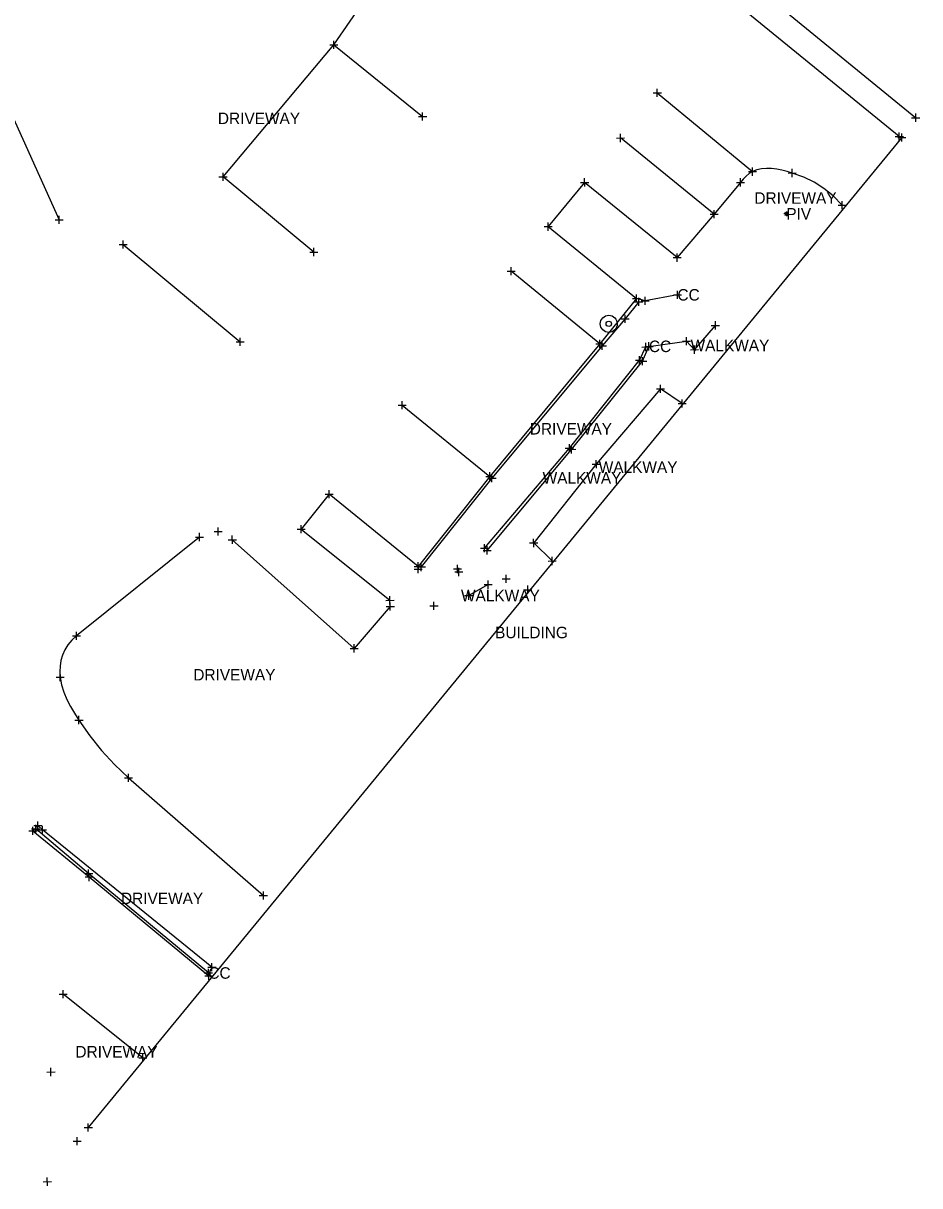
# Model space of a CAD drawing. Extents: x 1729655 to 1739338, y 463812 to 469501.
# Drawn here: x 1736064.5 to 1736204.6, y 466930.5 to 467112.2 of the extents above; entities that cross this region are included whole.
import ezdxf

# ---------------------------------------------------------------- set-up
doc = ezdxf.new("R2010")
doc.units = 0
for name, color, linetype in [('S_Bridge_Column_Round', 7, 'Continuous'), ('S_Bridge_Rail', 7, 'Continuous'), ('S_Buildings_Steps', 7, 'Continuous'), ('S_Ground_SpotElevation', 7, 'Continuous'), ('S_Property_Garden', 7, 'Continuous'), ('S_Roadway_Drive_Gravel', 7, 'Continuous'), ('S_Roadway_Drive_Paved', 7, 'Continuous'), ('S_Roadway_Edge_TW', 7, 'Continuous'), ('S_Roadway_Painted_Lines', 7, 'Continuous'), ('S_Roadway_Sidewalks', 7, 'Continuous'), ('S_Terrain_High_Points', 7, 'Continuous'), ('S_Trees_Bush_Line', 7, 'Continuous')]:
    doc.layers.add(name, color=color, linetype=linetype)

msp = doc.modelspace()

# ---------------------------------------------------------------- linework, layer by layer
at = {"layer": 'S_Bridge_Column_Round'}
for p, q in [((1736112.39, 467108.81), (1736113.66, 467108.81)), ((1736112.39, 467108.81), (1736113.66, 467108.81)), ((1736113.03, 467108.18), (1736113.03, 467109.45)), ((1736113.03, 467108.18), (1736113.03, 467109.45)), ((1736113.03, 467108.81), (1736113.03, 467108.81)), ((1736113.03, 467108.81), (1736113.03, 467108.81)), ((1736162.91, 467101.32), (1736164.19, 467101.32)), ((1736163.55, 467100.69), (1736163.55, 467101.96)), ((1736163.55, 467101.32), (1736163.55, 467101.32)), ((1736126.89, 467096.99), (1736126.89, 467098.26)), ((1736203.92, 467096.8), (1736203.92, 467098.08)), ((1736126.25, 467097.62), (1736127.53, 467097.62)), ((1736126.89, 467097.62), (1736126.89, 467097.62)), ((1736203.28, 467097.44), (1736204.55, 467097.44)), ((1736203.92, 467097.44), (1736203.92, 467097.44)), ((1736157.15, 467094.27), (1736158.42, 467094.28)), ((1736157.79, 467093.64), (1736157.79, 467094.91)), ((1736157.79, 467094.28), (1736157.79, 467094.28)), ((1736200.72, 467094.49), (1736202, 467094.5)), ((1736201.13, 467094.34), (1736202.4, 467094.34)), ((1736201.36, 467093.86), (1736201.36, 467095.13)), ((1736201.36, 467094.5), (1736201.36, 467094.5)), ((1736201.77, 467093.7), (1736201.76, 467094.98)), ((1736201.76, 467094.34), (1736201.76, 467094.34)), ((1736095.7, 467087.56), (1736095.7, 467088.83)), ((1736095.7, 467087.56), (1736095.7, 467088.83)), ((1736177.78, 467089.02), (1736179.05, 467089.02)), ((1736177.78, 467089.02), (1736179.05, 467089.02)), ((1736178.42, 467088.38), (1736178.42, 467089.65)), ((1736178.42, 467088.38), (1736178.42, 467089.65)), ((1736178.42, 467089.02), (1736178.42, 467089.02)), ((1736178.42, 467089.02), (1736178.42, 467089.02)), ((1736184, 467088.8), (1736185.27, 467088.81)), ((1736184.64, 467088.17), (1736184.63, 467089.44)), ((1736184.63, 467088.8), (1736184.63, 467088.8)), ((1736095.06, 467088.2), (1736096.34, 467088.2)), ((1736095.06, 467088.2), (1736096.34, 467088.2)), ((1736095.7, 467088.2), (1736095.7, 467088.2)), ((1736095.7, 467088.2), (1736095.7, 467088.2)), ((1736151.57, 467087.33), (1736152.84, 467087.33)), ((1736152.21, 467086.7), (1736152.2, 467087.97)), ((1736152.2, 467087.33), (1736152.2, 467087.33)), ((1736175.9, 467087.33), (1736177.17, 467087.33)), ((1736176.53, 467086.69), (1736176.53, 467087.97)), ((1736176.53, 467087.33), (1736176.53, 467087.33)), ((1736191.8, 467083.77), (1736193.08, 467083.78)), ((1736191.8, 467083.77), (1736193.08, 467083.78)), ((1736192.44, 467083.14), (1736192.44, 467084.41)), ((1736192.44, 467083.14), (1736192.44, 467084.41)), ((1736192.44, 467083.77), (1736192.44, 467083.77)), ((1736192.44, 467083.77), (1736192.44, 467083.77)), ((1736069.47, 467081.48), (1736070.74, 467081.48)), ((1736070.1, 467080.84), (1736070.1, 467082.12)), ((1736070.1, 467081.48), (1736070.1, 467081.48)), ((1736171.79, 467082.36), (1736173.06, 467082.37)), ((1736171.79, 467082.36), (1736173.06, 467082.37)), ((1736172.43, 467081.73), (1736172.42, 467083)), ((1736172.43, 467081.73), (1736172.42, 467083)), ((1736172.42, 467082.36), (1736172.42, 467082.36)), ((1736172.42, 467082.36), (1736172.42, 467082.36)), ((1736145.87, 467080.42), (1736147.15, 467080.42)), ((1736146.51, 467079.78), (1736146.51, 467081.06)), ((1736146.51, 467080.42), (1736146.51, 467080.42)), ((1736080.12, 467076.99), (1736080.11, 467078.27)), ((1736080.12, 467076.99), (1736080.11, 467078.27)), ((1736079.48, 467077.63), (1736080.75, 467077.63)), ((1736079.48, 467077.63), (1736080.75, 467077.63)), ((1736080.11, 467077.63), (1736080.11, 467077.63)), ((1736080.11, 467077.63), (1736080.11, 467077.63)), ((1736109.26, 467076.45), (1736110.53, 467076.45)), ((1736109.9, 467075.82), (1736109.89, 467077.09)), ((1736109.89, 467076.45), (1736109.89, 467076.45)), ((1736166.67, 467074.94), (1736166.66, 467076.22)), ((1736166.67, 467074.94), (1736166.66, 467076.22)), ((1736140.7, 467072.81), (1736140.7, 467074.08)), ((1736166.03, 467075.58), (1736167.3, 467075.58)), ((1736166.03, 467075.58), (1736167.3, 467075.58)), ((1736166.66, 467075.58), (1736166.66, 467075.58)), ((1736166.66, 467075.58), (1736166.66, 467075.58)), ((1736140.07, 467073.45), (1736141.34, 467073.45)), ((1736140.7, 467073.45), (1736140.7, 467073.45)), ((1736159.68, 467069.18), (1736160.95, 467069.19)), ((1736159.68, 467069.18), (1736160.95, 467069.19)), ((1736160.01, 467068.66), (1736161.28, 467068.67)), ((1736160.31, 467068.55), (1736160.31, 467069.82)), ((1736160.31, 467068.55), (1736160.31, 467069.82)), ((1736160.31, 467069.18), (1736160.31, 467069.18)), ((1736160.31, 467069.18), (1736160.31, 467069.18)), ((1736160.64, 467068.03), (1736160.64, 467069.3)), ((1736160.64, 467068.66), (1736160.64, 467068.66)), ((1736161.02, 467068.84), (1736162.3, 467068.84)), ((1736161.02, 467068.84), (1736162.3, 467068.84)), ((1736161.66, 467068.2), (1736161.66, 467069.47)), ((1736161.66, 467068.2), (1736161.66, 467069.47)), ((1736161.66, 467068.84), (1736161.66, 467068.84)), ((1736161.66, 467068.84), (1736161.66, 467068.84)), ((1736166.07, 467069.76), (1736167.34, 467069.76)), ((1736166.07, 467069.76), (1736167.34, 467069.76)), ((1736166.71, 467069.12), (1736166.7, 467070.4)), ((1736166.71, 467069.12), (1736166.7, 467070.4)), ((1736166.7, 467069.76), (1736166.7, 467069.76)), ((1736166.7, 467069.76), (1736166.7, 467069.76)), ((1736157.9, 467066.02), (1736159.17, 467066.03)), ((1736158.53, 467065.39), (1736158.53, 467066.66)), ((1736158.53, 467066.02), (1736158.53, 467066.02)), ((1736171.99, 467064.98), (1736173.26, 467064.98)), ((1736172.63, 467064.34), (1736172.63, 467065.62)), ((1736172.63, 467064.98), (1736172.63, 467064.98)), ((1736168.12, 467061.87), (1736168.12, 467063.14)), ((1736168.12, 467061.87), (1736168.12, 467063.14)), ((1736097.74, 467062.41), (1736099.01, 467062.41)), ((1736098.38, 467061.77), (1736098.37, 467063.05)), ((1736098.38, 467062.41), (1736098.38, 467062.41)), ((1736153.93, 467062.12), (1736155.2, 467062.12)), ((1736153.93, 467062.12), (1736155.2, 467062.12)), ((1736154.32, 467061.78), (1736155.59, 467061.78)), ((1736154.57, 467061.48), (1736154.56, 467062.75)), ((1736154.57, 467061.48), (1736154.56, 467062.75)), ((1736154.56, 467062.12), (1736154.56, 467062.12)), ((1736154.56, 467062.12), (1736154.56, 467062.12)), ((1736154.95, 467061.14), (1736154.95, 467062.42)), ((1736154.95, 467061.78), (1736154.95, 467061.78)), ((1736161.13, 467061.6), (1736162.4, 467061.61)), ((1736161.61, 467061.71), (1736162.88, 467061.71)), ((1736161.61, 467061.71), (1736162.88, 467061.71)), ((1736161.77, 467060.97), (1736161.76, 467062.24)), ((1736161.76, 467061.61), (1736161.76, 467061.61)), ((1736162.24, 467061.08), (1736162.24, 467062.35)), ((1736162.24, 467061.08), (1736162.24, 467062.35)), ((1736162.24, 467061.71), (1736162.24, 467061.71)), ((1736162.24, 467061.71), (1736162.24, 467061.71)), ((1736167.48, 467062.5), (1736168.76, 467062.51)), ((1736167.48, 467062.5), (1736168.76, 467062.51)), ((1736168.12, 467062.51), (1736168.12, 467062.51)), ((1736168.12, 467062.51), (1736168.12, 467062.51)), ((1736169.38, 467060.56), (1736169.38, 467061.83)), ((1736169.38, 467060.56), (1736169.38, 467061.83)), ((1736160.14, 467059.55), (1736161.42, 467059.55)), ((1736160.78, 467058.91), (1736160.78, 467060.19)), ((1736160.78, 467059.55), (1736160.78, 467059.55)), ((1736161.26, 467058.76), (1736161.26, 467060.03)), ((1736168.74, 467061.19), (1736170.01, 467061.2)), ((1736168.74, 467061.19), (1736170.01, 467061.2)), ((1736169.38, 467061.19), (1736169.38, 467061.19)), ((1736169.38, 467061.19), (1736169.38, 467061.19)), ((1736160.62, 467059.39), (1736161.9, 467059.39)), ((1736161.26, 467059.39), (1736161.26, 467059.39)), ((1736163.42, 467055.07), (1736164.69, 467055.07)), ((1736164.06, 467054.44), (1736164.06, 467055.71)), ((1736164.06, 467055.07), (1736164.06, 467055.07)), ((1736123.06, 467052.51), (1736124.33, 467052.51)), ((1736123.7, 467051.88), (1736123.7, 467053.15)), ((1736123.7, 467052.51), (1736123.7, 467052.51)), ((1736166.79, 467052.77), (1736168.07, 467052.78)), ((1736167.43, 467052.14), (1736167.43, 467053.41)), ((1736167.43, 467052.77), (1736167.43, 467052.77)), ((1736149.18, 467045.8), (1736150.45, 467045.81)), ((1736149.53, 467045.61), (1736150.8, 467045.62)), ((1736149.82, 467045.17), (1736149.81, 467046.44)), ((1736149.81, 467045.81), (1736149.81, 467045.81)), ((1736150.17, 467044.98), (1736150.16, 467046.25)), ((1736150.16, 467045.61), (1736150.16, 467045.61)), ((1736153.39, 467043.3), (1736154.66, 467043.31)), ((1736154.03, 467042.67), (1736154.02, 467043.94)), ((1736154.02, 467043.3), (1736154.02, 467043.3)), ((1736136.74, 467041.39), (1736138.02, 467041.39)), ((1736136.74, 467041.39), (1736138.02, 467041.39)), ((1736137.38, 467040.76), (1736137.38, 467042.03)), ((1736137.38, 467040.76), (1736137.38, 467042.03)), ((1736137.38, 467041.39), (1736137.38, 467041.39)), ((1736137.38, 467041.39), (1736137.38, 467041.39)), ((1736137.71, 467040.47), (1736137.71, 467041.74)), ((1736137.08, 467041.1), (1736138.35, 467041.1)), ((1736137.71, 467041.1), (1736137.71, 467041.1)), ((1736111.66, 467038.6), (1736112.93, 467038.6)), ((1736112.3, 467037.96), (1736112.29, 467039.24)), ((1736112.3, 467038.6), (1736112.3, 467038.6)), ((1736092.03, 467031.28), (1736092.03, 467032.55)), ((1736094.31, 467032.78), (1736095.58, 467032.78)), ((1736094.95, 467032.14), (1736094.94, 467033.42)), ((1736094.94, 467032.78), (1736094.94, 467032.78)), ((1736107.27, 467033.14), (1736108.54, 467033.15)), ((1736107.9, 467032.51), (1736107.9, 467033.78)), ((1736107.9, 467033.14), (1736107.9, 467033.14)), ((1736091.4, 467031.91), (1736092.67, 467031.91)), ((1736092.03, 467031.91), (1736092.03, 467031.91)), ((1736096.52, 467031.49), (1736097.79, 467031.49)), ((1736097.16, 467030.85), (1736097.15, 467032.13)), ((1736097.15, 467031.49), (1736097.15, 467031.49)), ((1736136.54, 467029.53), (1736136.54, 467030.81)), ((1736136.99, 467029.19), (1736136.98, 467030.46)), ((1736143.6, 467030.98), (1736144.87, 467030.98)), ((1736144.24, 467030.34), (1736144.23, 467031.62)), ((1736144.24, 467030.98), (1736144.24, 467030.98)), ((1736135.91, 467030.17), (1736137.18, 467030.17)), ((1736136.35, 467029.82), (1736137.62, 467029.83)), ((1736136.54, 467030.17), (1736136.54, 467030.17)), ((1736136.98, 467029.82), (1736136.98, 467029.82)), ((1736147.13, 467027.53), (1736147.13, 467028.8)), ((1736125.55, 467027.33), (1736126.82, 467027.33)), ((1736125.55, 467027.33), (1736126.82, 467027.33)), ((1736125.55, 467027.33), (1736126.82, 467027.33)), ((1736125.55, 467026.91), (1736126.83, 467026.91)), ((1736126.04, 467027.24), (1736127.32, 467027.24)), ((1736126.19, 467026.69), (1736126.19, 467027.96)), ((1736126.19, 467026.69), (1736126.19, 467027.96)), ((1736126.19, 467026.69), (1736126.19, 467027.96)), ((1736126.19, 467026.27), (1736126.19, 467027.55)), ((1736126.19, 467027.33), (1736126.19, 467027.33)), ((1736126.19, 467027.33), (1736126.19, 467027.33)), ((1736126.19, 467027.33), (1736126.19, 467027.33)), ((1736126.19, 467026.91), (1736126.19, 467026.91)), ((1736126.68, 467026.6), (1736126.68, 467027.88)), ((1736126.68, 467027.24), (1736126.68, 467027.24)), ((1736131.69, 467026.92), (1736132.97, 467026.92)), ((1736132.33, 467026.28), (1736132.33, 467027.56)), ((1736132.33, 467026.92), (1736132.33, 467026.92)), ((1736132.54, 467025.81), (1736132.53, 467027.09)), ((1736146.49, 467028.16), (1736147.77, 467028.17)), ((1736147.13, 467028.17), (1736147.13, 467028.17)), ((1736131.9, 467026.45), (1736133.17, 467026.45)), ((1736132.54, 467026.45), (1736132.54, 467026.45)), ((1736137.11, 467023.84), (1736137.11, 467025.11)), ((1736139.29, 467025.37), (1736140.56, 467025.38)), ((1736139.92, 467024.74), (1736139.92, 467026.01)), ((1736139.92, 467025.38), (1736139.92, 467025.38)), ((1736134.08, 467022.12), (1736134.08, 467023.39)), ((1736136.48, 467024.47), (1736137.75, 467024.48)), ((1736137.11, 467024.48), (1736137.11, 467024.48)), ((1736142.66, 467023.68), (1736143.94, 467023.68)), ((1736142.66, 467023.68), (1736143.94, 467023.68)), ((1736143.3, 467023.04), (1736143.3, 467024.31)), ((1736143.3, 467023.04), (1736143.3, 467024.31)), ((1736143.3, 467023.68), (1736143.3, 467023.68)), ((1736143.3, 467023.68), (1736143.3, 467023.68)), ((1736121.14, 467022.01), (1736122.42, 467022.02)), ((1736121.78, 467021.38), (1736121.78, 467022.65)), ((1736121.78, 467022.02), (1736121.78, 467022.02)), ((1736121.83, 467020.42), (1736121.83, 467021.69)), ((1736121.83, 467020.42), (1736121.83, 467021.69)), ((1736128.66, 467020.51), (1736128.66, 467021.79)), ((1736133.44, 467022.76), (1736134.71, 467022.76)), ((1736134.08, 467022.76), (1736134.08, 467022.76)), ((1736121.19, 467021.05), (1736122.47, 467021.05)), ((1736121.19, 467021.05), (1736122.47, 467021.05)), ((1736121.83, 467021.05), (1736121.83, 467021.05)), ((1736121.83, 467021.05), (1736121.83, 467021.05)), ((1736128.02, 467021.15), (1736129.29, 467021.15)), ((1736128.66, 467021.15), (1736128.66, 467021.15)), ((1736072.18, 467016.47), (1736073.45, 467016.47)), ((1736072.82, 467015.83), (1736072.81, 467017.11)), ((1736072.82, 467016.47), (1736072.82, 467016.47)), ((1736115.55, 467014.51), (1736116.82, 467014.51)), ((1736116.19, 467013.87), (1736116.18, 467015.15)), ((1736116.18, 467014.51), (1736116.18, 467014.51)), ((1736070.26, 467009.37), (1736070.26, 467010.65)), ((1736069.62, 467010.01), (1736070.9, 467010.01)), ((1736070.26, 467010.01), (1736070.26, 467010.01)), ((1736072.55, 467003.31), (1736073.83, 467003.31)), ((1736073.19, 467002.67), (1736073.19, 467003.95)), ((1736073.19, 467003.31), (1736073.19, 467003.31)), ((1736080.3, 466994.27), (1736081.58, 466994.27)), ((1736080.94, 466993.64), (1736080.94, 466994.91)), ((1736080.94, 466994.27), (1736080.94, 466994.27)), ((1736066.44, 466985.67), (1736066.43, 466986.94)), ((1736066.76, 466986.19), (1736066.76, 466987.47)), ((1736065.36, 466985.99), (1736066.64, 466985.99)), ((1736065.8, 466986.31), (1736067.07, 466986.31)), ((1736066, 466985.35), (1736066, 466986.62)), ((1736066, 466985.99), (1736066, 466985.99)), ((1736066.12, 466986.83), (1736067.4, 466986.83)), ((1736066.43, 466986.31), (1736066.43, 466986.31)), ((1736066.76, 466986.83), (1736066.76, 466986.83)), ((1736066.85, 466986.15), (1736068.12, 466986.15)), ((1736067.49, 466985.52), (1736067.48, 466986.79)), ((1736067.48, 466986.15), (1736067.48, 466986.15)), ((1736074.7, 466978.69), (1736074.7, 466979.97)), ((1736074.06, 466979.33), (1736075.34, 466979.33)), ((1736074.17, 466978.79), (1736075.44, 466978.79)), ((1736074.7, 466979.33), (1736074.7, 466979.33)), ((1736074.81, 466978.15), (1736074.8, 466979.42)), ((1736074.8, 466978.79), (1736074.8, 466978.79)), ((1736102.01, 466975.25), (1736102, 466976.53)), ((1736101.37, 466975.89), (1736102.64, 466975.89)), ((1736102.01, 466975.89), (1736102.01, 466975.89)), ((1736093.97, 466964.05), (1736093.97, 466965.33)), ((1736092.77, 466963.78), (1736094.05, 466963.78)), ((1736092.87, 466963.34), (1736094.14, 466963.35)), ((1736093.33, 466964.69), (1736094.61, 466964.69)), ((1736093.41, 466963.14), (1736093.41, 466964.42)), ((1736093.41, 466963.78), (1736093.41, 466963.78)), ((1736093.5, 466962.71), (1736093.5, 466963.98)), ((1736093.5, 466963.35), (1736093.5, 466963.35)), ((1736093.97, 466964.69), (1736093.97, 466964.69)), ((1736070.09, 466960.49), (1736071.36, 466960.49)), ((1736070.73, 466959.85), (1736070.72, 466961.12)), ((1736070.73, 466960.49), (1736070.73, 466960.49)), ((1736082.53, 466950.52), (1736083.81, 466950.53)), ((1736083.17, 466949.89), (1736083.17, 466951.16)), ((1736083.17, 466950.52), (1736083.17, 466950.52)), ((1736068.82, 466947.67), (1736068.82, 466948.94)), ((1736068.19, 466948.3), (1736069.46, 466948.31)), ((1736068.82, 466948.3), (1736068.82, 466948.3)), ((1736074.02, 466939.63), (1736075.29, 466939.63)), ((1736074.65, 466939), (1736074.65, 466940.27)), ((1736074.65, 466939.63), (1736074.65, 466939.63)), ((1736072.91, 466936.86), (1736072.91, 466938.13)), ((1736072.28, 466937.49), (1736073.55, 466937.49)), ((1736072.91, 466937.49), (1736072.91, 466937.49)), ((1736067.62, 466931.16), (1736068.89, 466931.17)), ((1736067.62, 466931.16), (1736068.89, 466931.17)), ((1736068.26, 466930.53), (1736068.25, 466931.8)), ((1736068.26, 466930.53), (1736068.25, 466931.8)), ((1736068.26, 466931.17), (1736068.26, 466931.17)), ((1736068.26, 466931.17), (1736068.26, 466931.17))]:
    msp.add_line(p, q, dxfattribs=at)
at = {"layer": 'S_Bridge_Rail'}
for radius in [1.33, 0.417]:
    msp.add_circle((1736155.97, 467065.23), radius, dxfattribs=at)
at = {"layer": 'S_Buildings_Steps'}
for p, q in [((1736184.1, 467082.42), (1736183.32, 467082.42)), ((1736183.97, 467082.16), (1736183.45, 467082.68)), ((1736183.97, 467082.68), (1736183.45, 467082.16)), ((1736183.71, 467082.81), (1736183.71, 467082.03))]:
    msp.add_line(p, q, dxfattribs=at)
at = {"layer": 'S_Ground_SpotElevation'}
for p, q in [((1736113.03, 467108.81), (1736125.25, 467126.71)), ((1736095.7, 467088.2), (1736113.03, 467108.81)), ((1736061.34, 467100.89), (1736070.1, 467081.48)), ((1736176.53, 467087.33), (1736172.42, 467082.36)), ((1736172.42, 467082.36), (1736166.66, 467075.58)), ((1736092.03, 467031.91), (1736072.82, 467016.47)), ((1736116.18, 467014.51), (1736097.15, 467031.49)), ((1736121.83, 467021.05), (1736116.18, 467014.51)), ((1736080.94, 466994.27), (1736102.01, 466975.89)), ((1736083.17, 466950.52), (1736070.73, 466960.49))]:
    msp.add_line(p, q, dxfattribs=at)
for points in [[(1736192.44, 467083.77), (1736191.04, 467085.21), (1736189.59, 467086.39), (1736188.06, 467087.36), (1736186.42, 467088.15), (1736184.63, 467088.8), (1736183.84, 467089.04), (1736183.03, 467089.25), (1736182.21, 467089.4), (1736181.39, 467089.5), (1736180.6, 467089.53), (1736179.83, 467089.46), (1736179.1, 467089.3), (1736178.42, 467089.02), (1736177.91, 467088.7), (1736177.43, 467088.3), (1736176.98, 467087.84), (1736176.53, 467087.33)], [(1736161.66, 467068.84), (1736160.31, 467069.18), (1736154.56, 467062.12), (1736137.38, 467041.39), (1736126.19, 467027.33)], [(1736072.82, 467016.47), (1736072.08, 467015.79), (1736071.47, 467015.05), (1736070.99, 467014.27), (1736070.63, 467013.45), (1736070.38, 467012.6), (1736070.25, 467011.74), (1736070.21, 467010.87), (1736070.26, 467010.01), (1736070.48, 467008.82), (1736070.84, 467007.66), (1736071.32, 467006.54), (1736071.88, 467005.43), (1736072.52, 467004.36), (1736073.19, 467003.31), (1736074.9, 467000.86), (1736076.73, 466998.55), (1736078.73, 466996.36), (1736080.94, 466994.27)], [(1736093.97, 466964.69), (1736067.48, 466986.15), (1736066.76, 466986.83), (1736066, 466985.99), (1736074.8, 466978.79), (1736093.5, 466963.35)]]:
    msp.add_lwpolyline(points, dxfattribs=at)
at = {"layer": 'S_Property_Garden'}
for p, q in [((1736161.26, 467059.39), (1736162.24, 467061.71)), ((1736150.16, 467045.61), (1736161.26, 467059.39)), ((1736136.98, 467029.82), (1736150.16, 467045.61)), ((1736126.19, 467027.33), (1736126.19, 467026.91)), ((1736137.11, 467024.48), (1736134.08, 467022.76))]:
    msp.add_line(p, q, dxfattribs=at)
for points in [[(1736168.12, 467062.51), (1736169.38, 467061.19)], [(1736167.43, 467052.77), (1736164.06, 467055.07), (1736154.02, 467043.3), (1736144.24, 467030.98), (1736147.13, 467028.17)]]:
    msp.add_lwpolyline(points, dxfattribs=at)
at = {"layer": 'S_Roadway_Drive_Gravel'}
for points in [[(1736157.74, 467135.5), (1736180.63, 467116.56), (1736203.92, 467097.44)], [(1736201.36, 467094.5), (1736175.48, 467115.59), (1736155.31, 467132.37)], [(1736113.03, 467108.81), (1736126.89, 467097.62)], [(1736163.55, 467101.32), (1736178.42, 467089.02)], [(1736172.42, 467082.36), (1736157.79, 467094.28)], [(1736109.89, 467076.45), (1736095.7, 467088.2)], [(1736166.66, 467075.58), (1736152.2, 467087.33), (1736146.51, 467080.42), (1736160.31, 467069.18)], [(1736080.11, 467077.63), (1736098.38, 467062.41)], [(1736154.56, 467062.12), (1736140.7, 467073.45)], [(1736123.7, 467052.51), (1736137.38, 467041.39)], [(1736126.19, 467027.33), (1736112.3, 467038.6), (1736107.9, 467033.14), (1736121.78, 467022.02)]]:
    msp.add_lwpolyline(points, dxfattribs=at)
at = {"layer": 'S_Roadway_Drive_Paved'}
msp.add_lwpolyline([(1736201.76, 467094.34), (1736074.65, 466939.63)], dxfattribs=at)
at = {"layer": 'S_Roadway_Edge_TW'}
for points in [[(1736166.7, 467069.76), (1736161.66, 467068.84)], [(1736162.24, 467061.71), (1736168.12, 467062.51)]]:
    msp.add_lwpolyline(points, dxfattribs=at)
at = {"layer": 'S_Roadway_Painted_Lines'}
for p, q in [((1736160.64, 467068.66), (1736158.53, 467066.02)), ((1736158.53, 467066.02), (1736154.95, 467061.78)), ((1736154.95, 467061.78), (1736137.71, 467041.1)), ((1736160.78, 467059.55), (1736161.76, 467061.61)), ((1736149.81, 467045.81), (1736160.78, 467059.55)), ((1736136.54, 467030.17), (1736149.81, 467045.81)), ((1736137.71, 467041.1), (1736126.68, 467027.24))]:
    msp.add_line(p, q, dxfattribs=at)
at = {"layer": 'S_Roadway_Sidewalks'}
msp.add_lwpolyline([(1736169.38, 467061.19), (1736172.63, 467064.98)], dxfattribs=at)
at = {"layer": 'S_Trees_Bush_Line'}
msp.add_lwpolyline([(1736093.41, 466963.78), (1736074.7, 466979.33), (1736066.43, 466986.31)], dxfattribs=at)

# ---------------------------------------------------------------- texts
at = {"layer": 'S_Terrain_High_Points'}
for s, p in [('DRIVEWAY', (1736094.9, 467096.44)), ('DRIVEWAY', (1736178.72, 467083.99)), ('PIV', (1736183.71, 467081.52)), ('CC', (1736166.7, 467068.86)), ('CC', (1736166.7, 467068.86)), ('CC', (1736162.24, 467060.81)), ('CC', (1736162.24, 467060.81)), ('WALKWAY', (1736168.75, 467060.95)), ('DRIVEWAY', (1736143.63, 467047.93)), ('WALKWAY', (1736154.4, 467041.94)), ('WALKWAY', (1736145.64, 467040.25)), ('WALKWAY', (1736132.88, 467021.86)), ('BUILDING', (1736138.21, 467016.09)), ('DRIVEWAY', (1736091.06, 467009.49)), ('DRIVEWAY', (1736079.76, 466974.54)), ('CC', (1736093.41, 466962.88)), ('DRIVEWAY', (1736072.64, 466950.57))]:
    msp.add_text(s, height=1.8, dxfattribs=at).set_placement(p)

doc.saveas('drawing.dxf')
